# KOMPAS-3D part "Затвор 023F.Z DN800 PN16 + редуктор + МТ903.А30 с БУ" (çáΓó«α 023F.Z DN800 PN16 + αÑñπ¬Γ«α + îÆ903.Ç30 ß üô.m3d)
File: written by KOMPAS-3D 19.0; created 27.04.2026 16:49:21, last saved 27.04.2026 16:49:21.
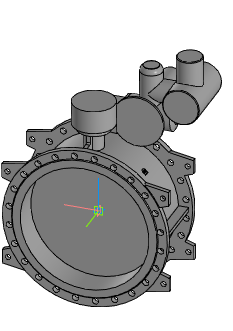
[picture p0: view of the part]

Document properties: Полное имя файла: ..\..\Затвор 023F.Z DN400-DN1600 + редуктор + МТ903\Затвор 023F.Z DN800 PN16 + редуктор + МТ903.А30 с БУ.a3d

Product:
- Part/product: Затвор 023F.Z DN800 PN16 + редуктор + МТ903.А30 с БУ
    Масса: 1083.49

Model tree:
1. Операция без истории:1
